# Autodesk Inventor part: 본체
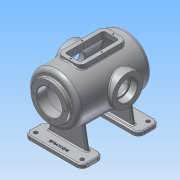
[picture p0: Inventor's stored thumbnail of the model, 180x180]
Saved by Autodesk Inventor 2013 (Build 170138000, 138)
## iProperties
Created: 2016-02
Part Number: 본체
Material: 알루미늄 6061
Document SubType Name: Modeling
Designer: mduedu
Density: 2.71 g/cm^3
Mass: 3305.57 g
Surface Area: 2487.04 cm^2
Volume: 1219.77 cm^3
Author: mduedu
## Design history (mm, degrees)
sketch "스케치2"
  geometry: L1 (0, 100)-(0, -100); L2 (65, -87.083)-(65, 100); L3 (65, 100)-(0, 100); A1 r 170 centre (0, 70) between (0, -100) and (65, -87.083); 2 further points
  constraints: 6 end point, 2 point on circle, 1 centre point, 1 coincident, 1 horizontal, 1 midpoint, 1 parallel, 1 point on line, 1 vertical
  dimensions: "d3" = 200 distance of L1.start L1.end; "d5" = 130 diameter of L2 L1; "d6" = 170 radius of A1
revolve "회전1" sketch "스케치2" stored, may be unused: angle "d7" = 90 deg
sketch "스케치3"
  geometry: C1 r 47.5 at (0, 0); 1 further point
  constraints: 1 centre point, 1 coincident
  dimensions: "d8" = 95 diameter of C1
extrude "돌출2" join sketch "스케치3" distance "d10" = 10; taper "d11" = 0 deg
sketch "스케치5"
  geometry: L1 (47.5, 110)-(47.5, 100) reference; L2 (47.5, 100)-(65, 100) reference; L3 (65, 100)-(65, -87.083) reference; L4 (-65, -87.083)-(-65, 100) reference; L5 (-65, 100)-(-47.5, 100) reference; L6 (-47.5, 100)-(-47.5, 110) reference; L7 (-47.5, 110)-(47.5, 110) reference; L8 (55, 85)-(55, -80.25); L9 (0, 85)-(55, 85); L10 (0, 85)-(0, -90); A1 r 170 centre (0, 70) between (-65, -87.083) and (0, -100) reference; A2 r 170 centre (0, 70) between (0, -100) and (65, -87.083) reference; A3 r 160 centre (0, 70) between (0, -90) and (55, -80.25); 1 further point
  constraints: 6 end point, 2 point on circle, 1 centre point, 1 parallel, 1 perpendicular, 1 point on line, 1 vertical
  dimensions: "d13" = 10 distance between parallel lines of L3 L8; "d14" = 10 radial gap between concentric circles of A3 A1; "d15" = 15 distance between parallel lines of L9 L2
revolve "회전2" sketch "스케치5" stored, may be unused: angle "d16" = 90 deg
hole "구멍1" diameter "d19" = 65; stored, may be unused: countersink angle "d23" = 90 deg, drill point angle "d25" = 118 deg; dims "d17" = 10, "d18" = 10, "d20" = 6, "d21" = 4, "d22" = 2, "d24" = 8
node "작업 평면1"
sketch "스케치6"
  geometry: L1 (47.5, 110)-(-47.5, 110) reference; C1 r 40 at (0, -17); 1 further point
  constraints: 1 centre point, 1 vertical alignment
  dimensions: "d27" = 80 diameter of C1; "d29" = 127 distance from line of C1.centre L1
extrude "돌출3" join sketch "스케치6" stored distance "d30" = 10; taper "d31" = 0 deg
hole "구멍2" diameter "d34" = 42; stored, may be unused: countersink angle "d38" = 90 deg, drill point angle "d40" = 118 deg; dims "d32" = 10, "d33" = 10, "d35" = 6, "d36" = 52, "d37" = 18, "d39" = 8
sketch "스케치7" dims "d41" = 65
  geometry: C1 r 40 at (0, 0) reference; 3 further points
  constraints: 2 vertical alignment, 1 coincident, 2 other
hole "구멍3" sketch "스케치7" at (0, 32.5) diameter "d43" = 3.242; stored, may be unused: countersink angle "d47" = 90 deg, drill point angle "d49" = 118 deg; dims "d44" = 11, "d45" = 13, "d46" = 18, "d48" = 13
sketch "스케치8" dims "d53" = 80
  geometry: 3 further points
  constraints: 2 vertical alignment, 1 coincident, 2 other
hole "구멍4" sketch "스케치8" at (0, 40) diameter "d56" = 3.242; stored, may be unused: countersink angle "d60" = 90 deg, drill point angle "d62" = 118 deg; dims "d57" = 11, "d58" = 13, "d59" = 18, "d61" = 13
fillet "모깎기1" dims "d66" = 10
fillet "모깎기2" dims "d67" = 3
fillet "모깎기3" dims "d68" = 0.3
chamfer "모따기1" distance "d69" = 1; stored, may be unused: second distance "d70" = 2, angle "d71" = 45 deg
node "작업 평면2"
sketch "스케치9"
  geometry: L1 (75, 100)-(-75, 100); L2 (-75, 100)-(-75, -100); L3 (-75, -100)-(75, -100); L4 (75, -100)-(75, 100); 1 further point
  constraints: 8 end point, 2 parallel, 1 horizontal, 1 perpendicular
  dimensions: "d73" = 200 distance of L3.end L1.start; "d75" = 150 distance of L2.end L3.end; "d76" = 100 distance from line of L1 point (0, 0); "d77" = 75 distance from line of L4 point (0, 0)
extrude "돌출4" join sketch "스케치9" distance "d78" = 10; taper "d79" = 0 deg
sketch "스케치10"
  geometry: L1 (-75, -100)-(75, -100) reference; L2 (75, 100)-(-75, 100) reference; L3 (0, -100)-(0, 100); L4 (-75, 100)-(-75, -100) reference; L5 (75, -100)-(75, 100) reference; L6 (-75, 0)-(75, 0); L7 (-50, -63)-(50, -63); L8 (50, -63)-(50, -55); L9 (50, -55)-(-50, -55); L10 (-50, -55)-(-50, -63); L11 (-50, 63)-(50, 63); L12 (50, 63)-(50, 55); L13 (50, 55)-(-50, 55); L14 (-50, 55)-(-50, 63); 1 further point
  constraints: 20 end point, 4 midpoint, 4 symmetric about line, 2 parallel, 1 horizontal, 1 perpendicular, 1 other
  dimensions: "d80" = 8 distance of L9.end L7.start; "d82" = 100 distance of L7.start L7.end; "d83" = 55 distance between parallel lines of L9 L6
extrude "돌출5" join sketch "스케치10" stored distance "d84" = 10; taper "d85" = 0 deg
feature "면 기울기1" dims angle "d86" = 10 deg
sketch "스케치11"
  geometry: L1 (-110, 55)-(-51.482, 55) reference; L2 (-110, -55)-(-51.482, -55) reference; L3 (-95, 55)-(-95, -55); L4 (-65, 90)-(-65, -80.25) reference; 1 further point
  constraints: 2 end point, 2 point on line, 1 perpendicular
  dimensions: "d87" = 30 distance between parallel lines of L3 L4
feature "리브1" sketch "스케치11" dims "d88" = 1, "d89" = 8, "d90" = 0, "d91" = 0, "d92" = 1, "d93" = 1
sketch "스케치12"
  geometry: L1 (-110, 55)-(-51.482, 55) reference; L2 (-110, -55)-(-51.482, -55) reference; L3 (-110, 100)-(-110, -100) reference; L4 (-120, 152)-(-120, -142) reference; L5 (-110, 45)-(-120, 45); L6 (-120, 45)-(-120, -45); L7 (-120, -45)-(-110, -45); L8 (-110, -45)-(-110, 45); 1 further point
  constraints: 8 end point, 2 parallel, 2 point on line, 1 horizontal, 1 perpendicular
  dimensions: "d94" = 10 distance between parallel lines of L7 L2; "d95" = 10 distance between parallel lines of L1 L5
extrude "돌출6" cut sketch "스케치12" stored distance "d96" = 10; taper "d97" = 0 deg
fillet "모깎기4" dims "d98" = 15
sketch "스케치13"
  geometry: C1 r 5 at (-60, -85); C2 r 5 at (60, -85); C3 r 5 at (60, 85); C4 r 5 at (-60, 85); A1 r 15 centre (-60, -85) between (-75, -85) and (-60, -100) reference; A2 r 15 centre (60, -85) between (60, -100) and (75, -85) reference; A3 r 15 centre (60, 85) between (75, 85) and (60, 100) reference; A4 r 15 centre (-60, 85) between (-60, 100) and (-75, 85) reference; 1 further point
  constraints: 4 centre point, 4 coincident, 3 equal radius
  dimensions: "d99" = 10 diameter of C1
extrude "돌출7" cut sketch "스케치13" stored distance "d101" = 10; taper "d102" = 0 deg
fillet "모깎기5" dims "d103" = 3, "d104" = 3
fillet "모깎기6" dims "d105" = 3
sketch "스케치14"
  geometry: L1 (-60, -100)-(60, -100) reference; 2 further points
  constraints: 1 vertical alignment, 1 other
  dimensions: "d106" = 15 distance from line of point (0, -85) L1
feature "엠보싱1" sketch "스케치14" dims "d3" = 200, "d5" = 130, "d6" = 170, "d14" = 10, "d107" = 0.5, "d108" = 0
node "작업 평면3"
sketch "스케치15"
  geometry: L1 (-30, 60)-(30, 60); L2 (30, 60)-(30, -60); L3 (30, -60)-(-30, -60); L4 (-30, -60)-(-30, 60); 2 further points
  constraints: 8 end point, 2 parallel, 1 horizontal, 1 midpoint, 1 perpendicular, 1 vertical alignment
  dimensions: "d110" = 60 distance of L2.end L3.end; "d112" = 60 distance from line of L3 point (0, 0); "d113" = 120 distance of L1.end L2.end
extrude "돌출8" join sketch "스케치15" stored distance "d114" = 10; taper "d115" = 0 deg
fillet "모깎기7" dims "d116" = 15
sketch "스케치16"
  geometry: L1 (-30, -45)-(-30, 45) reference; L2 (-15, 60)-(15, 60) reference; L3 (30, 45)-(30, -45) reference; L4 (15, -60)-(-15, -60) reference; L5 (15, 50)-(-15, 50); L6 (-20, 45)-(-20, -45); L7 (-15, -50)-(15, -50); L8 (20, -45)-(20, 45); A1 r 15 centre (-15, -45) between (-30, -45) and (-15, -60) reference; A2 r 15 centre (-15, 45) between (-15, 60) and (-30, 45) reference; A3 r 15 centre (15, 45) between (30, 45) and (15, 60) reference; A4 r 15 centre (15, -45) between (15, -60) and (30, -45) reference; A5 r 5 centre (-15, 45) between (-15, 50) and (-20, 45); A6 r 5 centre (-15, -45) between (-20, -45) and (-15, -50); A7 r 5 centre (15, -45) between (15, -50) and (20, -45); A8 r 5 centre (15, 45) between (20, 45) and (15, 50); 1 further point
  constraints: 8 end point, 8 point on circle, 4 centre point, 7 other
  dimensions: "d117" = 10 distance between parallel lines of L6 L1
extrude "돌출9" cut sketch "스케치16" stored distance "d118" = 10; taper "d119" = 0 deg
fillet "모깎기8" dims "d120" = 3
sketch "스케치17"
  geometry: L1 (-30, -45)-(-30, 45) reference; L2 (-15, 60)-(15, 60) reference; L3 (30, 45)-(30, -45) reference; L4 (15, -60)-(-15, -60) reference; L5 (20, -45)-(20, 45) reference; L6 (15, 50)-(-15, 50) reference; L7 (-20, 45)-(-20, -45) reference; L8 (-15, -50)-(15, -50) reference; L9 (15, 55)-(-15, 55); L10 (-25, 45)-(-25, -45); L11 (-15, -55)-(15, -55); L12 (25, -45)-(25, 45); A1 r 15 centre (-15, 45) between (-15, 60) and (-30, 45) reference; A2 r 15 centre (15, 45) between (30, 45) and (15, 60) reference; A3 r 15 centre (15, -45) between (15, -60) and (30, -45) reference; A4 r 15 centre (-15, -45) between (-30, -45) and (-15, -60) reference; A5 r 5 centre (15, -45) between (15, -50) and (20, -45) reference; A6 r 5 centre (15, 45) between (20, 45) and (15, 50) reference; A7 r 5 centre (-15, 45) between (-15, 50) and (-20, 45) reference; A8 r 5 centre (-15, -45) between (-20, -45) and (-15, -50) reference; A9 r 10 centre (-15, 45) between (-15, 55) and (-25, 45); A10 r 10 centre (-15, -45) between (-25, -45) and (-15, -55); A11 r 10 centre (15, -45) between (15, -55) and (25, -45); A12 r 10 centre (15, 45) between (25, 45) and (15, 55); 5 further points
  constraints: 8 end point, 8 point on circle, 4 centre point, 4 midpoint, 7 other
  dimensions: "d121" = 5 distance between parallel lines of L10 L1
hole "구멍5" sketch "스케치17" at (0, 55), (25, 0), (0, -55), (-25, 0) diameter "d122" = 3.242; stored, may be unused: countersink angle "d126" = 90 deg, drill point angle "d128" = 118 deg; dims "d123" = 9, "d124" = 13, "d125" = 18, "d127" = 11
fillet "모깎기9" dims "d129" = 3
node "솔리드2"
pattern_circular "원형 패턴1" dims angle "d51" = 360 deg
mirror "대칭1"
pattern_circular "원형 패턴2" dims angle "d64" = 360 deg
node "절단 모서리 투영1"
node "절단 모서리 투영2"
node "절단 모서리 투영3"
other parameters: "d26" = 75
